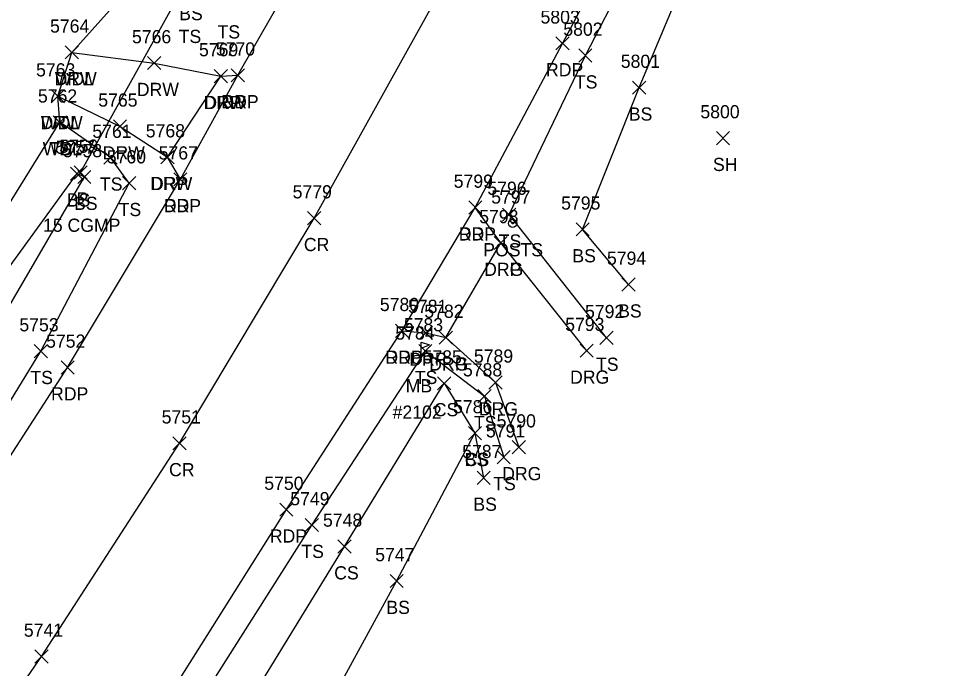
# Model space of a CAD drawing. Extents: x 1611797 to 1633212, y 298978 to 305475.
# Drawn here: x 1622570.5 to 1622713.1, y 301333.3 to 301431.8 of the extents above; entities that cross this region are included whole.
import ezdxf

# ---------------------------------------------------------------- set-up
doc = ezdxf.new("R2010")
doc.units = 0
for name, color, linetype in [('D_A', 7, 'Continuous'), ('D_C', 7, 'Continuous'), ('D_I', 7, 'Continuous'), ('D_TIC', 7, 'Continuous'), ('DCP', 7, 'Continuous'), ('L_A', 7, 'Continuous'), ('L_C', 7, 'Continuous'), ('L_I', 7, 'Continuous'), ('L_TIC', 7, 'Continuous'), ('LAWA', 7, 'Continuous'), ('LELB', 7, 'Continuous'), ('LMB', 7, 'Continuous'), ('LPST', 7, 'Continuous'), ('P_A', 7, 'Continuous'), ('P_I', 7, 'Continuous'), ('P_TIC', 7, 'Continuous'), ('PET', 7, 'Continuous'), ('PRC', 7, 'Continuous'), ('R_A', 7, 'Continuous'), ('R_I', 7, 'Continuous'), ('R_TIC', 7, 'Continuous'), ('RDG', 7, 'Continuous'), ('RDP', 7, 'Continuous'), ('RDW', 7, 'Continuous')]:
    doc.layers.add(name, color=color, linetype=linetype)

msp = doc.modelspace()

# ---------------------------------------------------------------- linework, layer by layer
at = {"layer": 'D_TIC'}
for points in [[(1622578.88, 301407.46), (1622580.88, 301409.46)], [(1622580.88, 301407.46), (1622578.88, 301409.46)]]:
    msp.add_lwpolyline(points, dxfattribs=at)
at = {"layer": 'DCP'}
msp.add_lwpolyline([(1622579.88, 301408.46), (1622595.74, 301437.07)], dxfattribs=at)
at = {"layer": 'L_TIC'}
for points in [[(1622577.56, 301425.68), (1622579.56, 301427.68)], [(1622579.56, 301425.68), (1622577.56, 301427.68)], [(1622655.41, 301425.2), (1622657.41, 301427.2)], [(1622657.41, 301425.2), (1622655.41, 301427.2)], [(1622663.56, 301420.33), (1622665.56, 301422.33)], [(1622665.56, 301420.33), (1622663.56, 301422.33)], [(1622575.44, 301419.03), (1622577.44, 301421.03)], [(1622577.44, 301419.03), (1622575.44, 301421.03)], [(1622575.72, 301415.07), (1622577.72, 301417.07)], [(1622577.72, 301415.07), (1622575.72, 301417.07)], [(1622575.72, 301415.07), (1622577.72, 301417.07)], [(1622577.72, 301415.07), (1622575.72, 301417.07)], [(1622676.27, 301412.68), (1622678.27, 301414.68)], [(1622678.27, 301412.68), (1622676.27, 301414.68)], [(1622583.4, 301409.71), (1622585.4, 301411.71)], [(1622585.4, 301409.71), (1622583.4, 301411.71)], [(1622578.34, 301407.29), (1622580.34, 301409.29)], [(1622580.34, 301407.29), (1622578.34, 301409.29)], [(1622579.45, 301406.78), (1622581.45, 301408.78)], [(1622581.45, 301406.78), (1622579.45, 301408.78)], [(1622579.45, 301406.78), (1622581.45, 301408.78)], [(1622581.45, 301406.78), (1622579.45, 301408.78)], [(1622586.24, 301405.84), (1622588.24, 301407.84)], [(1622588.24, 301405.84), (1622586.24, 301407.84)], [(1622643.87, 301401.07), (1622645.87, 301403.07)], [(1622645.87, 301401.07), (1622643.87, 301403.07)], [(1622655, 301398.83), (1622657, 301400.83)], [(1622657, 301398.83), (1622655, 301400.83)], [(1622661.94, 301390.46), (1622663.94, 301392.46)], [(1622663.94, 301390.46), (1622661.94, 301392.46)], [(1622658.62, 301382.37), (1622660.62, 301384.37)], [(1622660.62, 301382.37), (1622658.62, 301384.37)], [(1622572.86, 301380.36), (1622574.86, 301382.36)], [(1622574.86, 301380.36), (1622572.86, 301382.36)], [(1622631.15, 301380.37), (1622633.15, 301382.37)], [(1622633.15, 301380.37), (1622631.15, 301382.37)], [(1622633.99, 301375.48), (1622635.99, 301377.48)], [(1622635.99, 301375.48), (1622633.99, 301377.48)], [(1622640.11, 301373.53), (1622642.11, 301375.53)], [(1622642.11, 301373.53), (1622640.11, 301375.53)], [(1622638.67, 301367.93), (1622640.67, 301369.93)], [(1622640.67, 301367.93), (1622638.67, 301369.93)], [(1622638.67, 301367.93), (1622640.67, 301369.93)], [(1622640.67, 301367.93), (1622638.67, 301369.93)], [(1622643.03, 301364.27), (1622645.03, 301366.27)], [(1622645.03, 301364.27), (1622643.03, 301366.27)], [(1622639.99, 301361.14), (1622641.99, 301363.14)], [(1622641.99, 301361.14), (1622639.99, 301363.14)], [(1622613.94, 301353.98), (1622615.94, 301355.98)], [(1622615.94, 301353.98), (1622613.94, 301355.98)], [(1622618.89, 301350.73), (1622620.89, 301352.73)], [(1622620.89, 301350.73), (1622618.89, 301352.73)], [(1622626.8, 301345.49), (1622628.8, 301347.49)], [(1622628.8, 301345.49), (1622626.8, 301347.49)]]:
    msp.add_lwpolyline(points, dxfattribs=at)
at = {"layer": 'LAWA'}
msp.add_lwpolyline([(1622387.76, 301179.05), (1622397.07, 301179.12), (1622427.65, 301209.9), (1622449.62, 301231.58), (1622470.34, 301267.63), (1622492.33, 301297.51), (1622515.41, 301331.49), (1622538.47, 301358.93), (1622560.23, 301389.57), (1622576.72, 301416.07), (1622576.44, 301420.03), (1622578.56, 301426.68), (1622588.66, 301437.97), (1622599.63, 301454.27), (1622615.5, 301489.08), (1622629.31, 301519.57), (1622648.55, 301554.37)], dxfattribs=at)
at = {"layer": 'LELB'}
for points in [[(1622659.62, 301383.37), (1622644.87, 301402.07), (1622656.41, 301426.2), (1622674.48, 301461.14), (1622688.67, 301491.39), (1622700.72, 301519.47), (1622707.11, 301519.51), (1622713.09, 301516.74), (1622710.22, 301509.3)], [(1622662.94, 301391.46), (1622656, 301399.83), (1622664.56, 301421.33), (1622679.22, 301456.3), (1622694.47, 301488.4), (1622708.37, 301517.84), (1622709.31, 301517.52), (1622708.29, 301515.37)], [(1622303.98, 301104.59), (1622310.78, 301099.33), (1622319.48, 301096.25), (1622326.26, 301097.34), (1622347.55, 301114.38), (1622375.51, 301140.08), (1622405.76, 301169.1), (1622437.3, 301200.54), (1622458.43, 301224.95), (1622484.45, 301256.27), (1622508.57, 301286.02), (1622531.26, 301316.99), (1622553.65, 301348.32), (1622573.86, 301381.36), (1622587.24, 301406.84), (1622584.4, 301410.71), (1622576.72, 301416.07)], [(1622449.62, 301231.58), (1622466.76, 301250.92), (1622475.9, 301263.33), (1622499.11, 301292.58), (1622520.81, 301325.55), (1622542.36, 301355.63), (1622564.75, 301388.23), (1622579.34, 301408.29), (1622580.45, 301407.78)], [(1622305.52, 301107.15), (1622315.07, 301105.99), (1622317.12, 301104.2), (1622343.27, 301121.96), (1622371.22, 301146.89), (1622399.94, 301174.87), (1622430.59, 301207.07), (1622451.89, 301229.58), (1622468.36, 301249.15), (1622478.54, 301261.07), (1622501.72, 301291.08), (1622524.3, 301323.22), (1622546.27, 301353.28), (1622567.71, 301385.93), (1622580.45, 301407.78)], [(1622141.83, 300898.34), (1622139.55, 300912.95), (1622151.09, 300921.4), (1622196.53, 300946.85), (1622234.34, 300970.61), (1622271.97, 300994.63), (1622303.88, 301017.35), (1622337.87, 301043.51), (1622376.19, 301076.15), (1622406.41, 301102.71), (1622438.28, 301133.32), (1622472.59, 301167.8), (1622503.26, 301203.44), (1622524.06, 301228.28), (1622546.3, 301255.74), (1622570.57, 301288.87), (1622594.14, 301322.09), (1622614.94, 301354.98), (1622632.15, 301381.37), (1622641.11, 301374.53), (1622644.03, 301365.27)], [(1622154.74, 300907.48), (1622202.55, 300938.53), (1622239.36, 300963.45), (1622279.71, 300983.49), (1622308.78, 301010.44), (1622344.44, 301040.69), (1622379.56, 301071), (1622416.39, 301093.76), (1622447.98, 301125.69), (1622481.31, 301160.51), (1622517.14, 301198.88), (1622530.23, 301223.45), (1622553.77, 301249.54), (1622576.06, 301285.09), (1622599.23, 301317.97), (1622619.89, 301351.73), (1622634.99, 301376.48), (1622639.67, 301368.93)], [(1622587.21, 301277.1), (1622608.65, 301311.43), (1622627.8, 301346.49), (1622639.67, 301368.93), (1622640.99, 301362.14)]]:
    msp.add_lwpolyline(points, dxfattribs=at)
at = {"layer": 'LMB'}
for p, q in [((1622631.51, 301382.71), (1622632.8, 301382.33)), ((1622631.52, 301380.12), (1622631.52, 301382.72)), ((1622631.52, 301381.81), (1622632.8, 301382.32)), ((1622630.86, 301380.11), (1622630.86, 301380.11))]:
    msp.add_line(p, q, dxfattribs=at)
msp.add_circle((1622630.86, 301380.11), 0.656, dxfattribs=at)
at = {"layer": 'LPST'}
for radius in [0.625, 0.0833]:
    msp.add_circle((1622645.39, 301400.74), radius, dxfattribs=at)
at = {"layer": 'P_TIC'}
for points in [[(1622651.95, 301427.05), (1622653.95, 301429.05)], [(1622653.95, 301427.05), (1622651.95, 301429.05)], [(1622602.73, 301422.2), (1622604.73, 301424.2)], [(1622604.73, 301422.2), (1622602.73, 301424.2)], [(1622594.01, 301406.43), (1622596.01, 301408.43)], [(1622596.01, 301406.43), (1622594.01, 301408.43)], [(1622638.72, 301402.14), (1622640.72, 301404.14)], [(1622640.72, 301402.14), (1622638.72, 301404.14)], [(1622614.3, 301400.53), (1622616.3, 301402.53)], [(1622616.3, 301400.53), (1622614.3, 301402.53)], [(1622627.6, 301383.44), (1622629.6, 301385.44)], [(1622629.6, 301383.44), (1622627.6, 301385.44)], [(1622576.91, 301377.88), (1622578.91, 301379.88)], [(1622578.91, 301377.88), (1622576.91, 301379.88)], [(1622593.86, 301366.38), (1622595.86, 301368.38)], [(1622595.86, 301366.38), (1622593.86, 301368.38)], [(1622610.08, 301356.32), (1622612.08, 301358.32)], [(1622612.08, 301356.32), (1622610.08, 301358.32)], [(1622572.96, 301334.04), (1622574.96, 301336.04)], [(1622574.96, 301334.04), (1622572.96, 301336.04)]]:
    msp.add_lwpolyline(points, dxfattribs=at)
at = {"layer": 'PET'}
for points in [[(1622408.25, 301165.87), (1622439.39, 301198.04), (1622461.95, 301222.58), (1622487.93, 301253.76), (1622511.51, 301284.23), (1622534.35, 301314.53), (1622556.78, 301346.23), (1622577.91, 301378.88), (1622595.01, 301407.43), (1622603.73, 301423.2), (1622617.19, 301446.82), (1622634.21, 301479.77), (1622648.26, 301509.67), (1622665.21, 301547.65)], [(1622403.36, 301105.61), (1622435.21, 301136.14), (1622468.93, 301170.7), (1622500.38, 301205.45), (1622521.19, 301230.71), (1622543.38, 301258.33), (1622567.24, 301290.95), (1622590.49, 301324.58), (1622611.08, 301357.32), (1622628.6, 301384.44), (1622639.72, 301403.14), (1622652.95, 301428.05), (1622671.36, 301462.7), (1622686.07, 301493.28), (1622698.78, 301521.43), (1622708.15, 301542.48)]]:
    msp.add_lwpolyline(points, dxfattribs=at)
at = {"layer": 'PRC'}
msp.add_lwpolyline([(1622391.65, 301120.64), (1622424.38, 301151.76), (1622455.13, 301183.21), (1622477.75, 301209.09), (1622504, 301239.92), (1622528.25, 301271.13), (1622551.53, 301302.46), (1622573.96, 301335.04), (1622594.86, 301367.38), (1622615.3, 301401.53), (1622634.9, 301436.89), (1622652.67, 301471.55), (1622666.77, 301501.34), (1622684.44, 301540.78)], dxfattribs=at)
at = {"layer": 'R_TIC'}
for points in [[(1622577.56, 301425.68), (1622579.56, 301427.68)], [(1622579.56, 301425.68), (1622577.56, 301427.68)], [(1622590.03, 301424.06), (1622592.03, 301426.06)], [(1622592.03, 301424.06), (1622590.03, 301426.06)], [(1622600.15, 301422.08), (1622602.15, 301424.08)], [(1622602.15, 301422.08), (1622600.15, 301424.08)], [(1622600.15, 301422.08), (1622602.15, 301424.08)], [(1622602.15, 301422.08), (1622600.15, 301424.08)], [(1622602.73, 301422.2), (1622604.73, 301424.2)], [(1622604.73, 301422.2), (1622602.73, 301424.2)], [(1622575.44, 301419.03), (1622577.44, 301421.03)], [(1622577.44, 301419.03), (1622575.44, 301421.03)], [(1622584.86, 301414.45), (1622586.86, 301416.45)], [(1622586.86, 301414.45), (1622584.86, 301416.45)], [(1622592.06, 301409.78), (1622594.06, 301411.78)], [(1622594.06, 301409.78), (1622592.06, 301411.78)], [(1622592.06, 301409.78), (1622594.06, 301411.78)], [(1622594.06, 301409.78), (1622592.06, 301411.78)], [(1622594.01, 301406.43), (1622596.01, 301408.43)], [(1622596.01, 301406.43), (1622594.01, 301408.43)], [(1622638.72, 301402.14), (1622640.72, 301404.14)], [(1622640.72, 301402.14), (1622638.72, 301404.14)], [(1622642.57, 301396.77), (1622644.57, 301398.77)], [(1622644.57, 301396.77), (1622642.57, 301398.77)], [(1622642.57, 301396.77), (1622644.57, 301398.77)], [(1622644.57, 301396.77), (1622642.57, 301398.77)], [(1622627.6, 301383.44), (1622629.6, 301385.44)], [(1622629.6, 301383.44), (1622627.6, 301385.44)], [(1622631.22, 301383.15), (1622633.22, 301385.15)], [(1622633.22, 301383.15), (1622631.22, 301385.15)], [(1622634.25, 301382.41), (1622636.25, 301384.41)], [(1622636.25, 301382.41), (1622634.25, 301384.41)], [(1622634.25, 301382.41), (1622636.25, 301384.41)], [(1622636.25, 301382.41), (1622634.25, 301384.41)], [(1622655.61, 301380.42), (1622657.61, 301382.42)], [(1622657.61, 301380.42), (1622655.61, 301382.42)], [(1622641.78, 301375.61), (1622643.78, 301377.61)], [(1622643.78, 301375.61), (1622641.78, 301377.61)], [(1622645.31, 301365.78), (1622647.31, 301367.78)], [(1622647.31, 301365.78), (1622645.31, 301367.78)]]:
    msp.add_lwpolyline(points, dxfattribs=at)
at = {"layer": 'RDG'}
for points in [[(1622656.61, 301381.42), (1622643.57, 301397.77)], [(1622635.25, 301383.41), (1622642.78, 301376.61), (1622646.31, 301366.78)]]:
    msp.add_lwpolyline(points, dxfattribs=at)
at = {"layer": 'RDP'}
for points in [[(1622595.01, 301407.43), (1622593.06, 301410.78), (1622601.15, 301423.08), (1622603.73, 301423.2)], [(1622628.6, 301384.44), (1622632.22, 301384.15), (1622635.25, 301383.41), (1622643.57, 301397.77), (1622639.72, 301403.14)]]:
    msp.add_lwpolyline(points, dxfattribs=at)
at = {"layer": 'RDW'}
for points in [[(1622578.56, 301426.68), (1622591.03, 301425.06), (1622601.15, 301423.08)], [(1622576.44, 301420.03), (1622585.86, 301415.45), (1622593.06, 301410.78)]]:
    msp.add_lwpolyline(points, dxfattribs=at)

# ---------------------------------------------------------------- texts
at = {"layer": 'D_A'}
msp.add_text('P', height=2, dxfattribs=at).set_placement((1622579.26, 301403.46))
at = {"layer": 'D_C'}
msp.add_text('15 CGMP', height=2, dxfattribs=at).set_placement((1622574.18, 301399.46))
at = {"layer": 'D_I'}
msp.add_text('5759', height=2, dxfattribs=at).set_placement((1622576.62, 301411.46))
at = {"layer": 'L_A'}
for s, p in [('BS', (1622594.83, 301431.56)), ('TS', (1622594.75, 301428.1)), ('TS', (1622600.64, 301428.79)), ('WDL', (1622575.98, 301421.68)), ('TS', (1622654.82, 301421.2)), ('BS', (1622663, 301416.33)), ('WDL', (1622573.85, 301415.03)), ('WDL', (1622574.13, 301411.07)), ('TS', (1622575.13, 301411.07)), ('SH', (1622675.76, 301408.68)), ('TS', (1622582.81, 301405.71)), ('BS', (1622577.78, 301403.29)), ('BS', (1622578.89, 301402.78)), ('BS', (1622578.89, 301402.78)), ('TS', (1622585.65, 301401.84)), ('TS', (1622643.28, 301397.07)), ('POSTS', (1622640.93, 301395.74)), ('BS', (1622654.44, 301394.83)), ('BS', (1622661.38, 301386.46)), ('TS', (1622658.03, 301378.37)), ('TS', (1622572.27, 301376.36)), ('TS', (1622630.55, 301376.37)), ('MB', (1622629.17, 301375.11)), ('CS', (1622633.43, 301371.48)), ('TS', (1622639.52, 301369.53)), ('CS', (1622638.11, 301363.93)), ('BS', (1622638.11, 301363.93)), ('TS', (1622642.44, 301360.27)), ('BS', (1622639.43, 301357.14)), ('TS', (1622613.35, 301349.98)), ('CS', (1622618.33, 301346.73)), ('BS', (1622626.24, 301341.49))]:
    msp.add_text(s, height=2, dxfattribs=at).set_placement(p)
at = {"layer": 'L_C'}
msp.add_text('#2102', height=2, dxfattribs=at).set_placement((1622627.19, 301371.11))
at = {"layer": 'L_I'}
for s, p in [('5764', (1622575.25, 301429.68)), ('5802', (1622653.07, 301429.2)), ('5801', (1622661.78, 301424.33)), ('5763', (1622573.13, 301423.03)), ('5762', (1622573.41, 301419.07)), ('5762', (1622573.41, 301419.07)), ('5800', (1622673.85, 301416.68)), ('5761', (1622581.66, 301413.71)), ('5757', (1622576.08, 301411.29)), ('5758', (1622577.19, 301410.78)), ('5758', (1622577.19, 301410.78)), ('5760', (1622583.85, 301409.84)), ('5796', (1622641.55, 301405.07)), ('5797', (1622642.13, 301403.74)), ('5795', (1622652.74, 301402.83)), ('5794', (1622659.68, 301394.46)), ('5792', (1622656.36, 301386.37)), ('5753', (1622570.6, 301384.36)), ('5783', (1622628.89, 301384.37)), ('5784', (1622627.6, 301383.11)), ('5785', (1622631.73, 301379.48)), ('5788', (1622637.85, 301377.53)), ('5786', (1622636.35, 301371.93)), ('5786', (1622636.35, 301371.93)), ('5791', (1622641.34, 301368.27)), ('5787', (1622637.73, 301365.14)), ('5749', (1622611.67, 301357.98)), ('5748', (1622616.63, 301354.73)), ('5747', (1622624.54, 301349.49))]:
    msp.add_text(s, height=2, dxfattribs=at).set_placement(p)
at = {"layer": 'P_A'}
for s, p in [('RDP', (1622650.44, 301423.05)), ('RDP', (1622601.22, 301418.2)), ('RDP', (1622592.5, 301402.43)), ('RDP', (1622637.21, 301398.14)), ('CR', (1622613.73, 301396.53)), ('RDP', (1622626.09, 301379.44)), ('RDP', (1622575.4, 301373.88)), ('CR', (1622593.29, 301362.38)), ('RDP', (1622608.57, 301352.32))]:
    msp.add_text(s, height=2, dxfattribs=at).set_placement(p)
at = {"layer": 'P_I'}
for s, p in [('5803', (1622649.61, 301431.05)), ('5770', (1622600.38, 301426.2)), ('5767', (1622591.71, 301410.43)), ('5799', (1622636.45, 301406.14)), ('5779', (1622612.03, 301404.53)), ('5780', (1622625.25, 301387.44)), ('5752', (1622574.65, 301381.88)), ('5751', (1622592.17, 301370.38)), ('5750', (1622607.73, 301360.32)), ('5741', (1622571.27, 301338.04))]:
    msp.add_text(s, height=2, dxfattribs=at).set_placement(p)
at = {"layer": 'R_A'}
for s, p in [('DRW', (1622575.93, 301421.68)), ('DRW', (1622588.4, 301420.06)), ('DRW', (1622598.52, 301418.08)), ('DRP', (1622598.64, 301418.08)), ('DRP', (1622601.22, 301418.2)), ('DRW', (1622573.81, 301415.03)), ('DRW', (1622583.23, 301410.45)), ('DRW', (1622590.43, 301405.78)), ('DRP', (1622590.55, 301405.78)), ('DRP', (1622592.5, 301402.43)), ('DRP', (1622637.21, 301398.14)), ('DRG', (1622641.06, 301392.77)), ('DRP', (1622641.06, 301392.77)), ('DRP', (1622626.09, 301379.44)), ('DRP', (1622629.71, 301379.15)), ('DRG', (1622632.74, 301378.41)), ('DRP', (1622632.74, 301378.41)), ('DRG', (1622654.09, 301376.42)), ('DRG', (1622640.27, 301371.61)), ('DRG', (1622643.8, 301361.78))]:
    msp.add_text(s, height=2, dxfattribs=at).set_placement(p)
at = {"layer": 'R_I'}
for s, p in [('5764', (1622575.25, 301429.68)), ('5766', (1622587.67, 301428.06)), ('5770', (1622600.38, 301426.2)), ('5769', (1622597.83, 301426.08)), ('5769', (1622597.83, 301426.08)), ('5763', (1622573.13, 301423.03)), ('5765', (1622582.56, 301418.45)), ('5768', (1622589.76, 301413.78)), ('5768', (1622589.76, 301413.78)), ('5767', (1622591.71, 301410.43)), ('5799', (1622636.45, 301406.14)), ('5798', (1622640.31, 301400.77)), ('5798', (1622640.31, 301400.77)), ('5780', (1622625.25, 301387.44)), ('5781', (1622629.53, 301387.15)), ('5782', (1622631.99, 301386.41)), ('5782', (1622631.99, 301386.41)), ('5793', (1622653.35, 301384.42)), ('5789', (1622639.51, 301379.61)), ('5790', (1622642.96, 301369.78))]:
    msp.add_text(s, height=2, dxfattribs=at).set_placement(p)

doc.saveas('drawing.dxf')
